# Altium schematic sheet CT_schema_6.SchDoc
size 368 x 245 mm
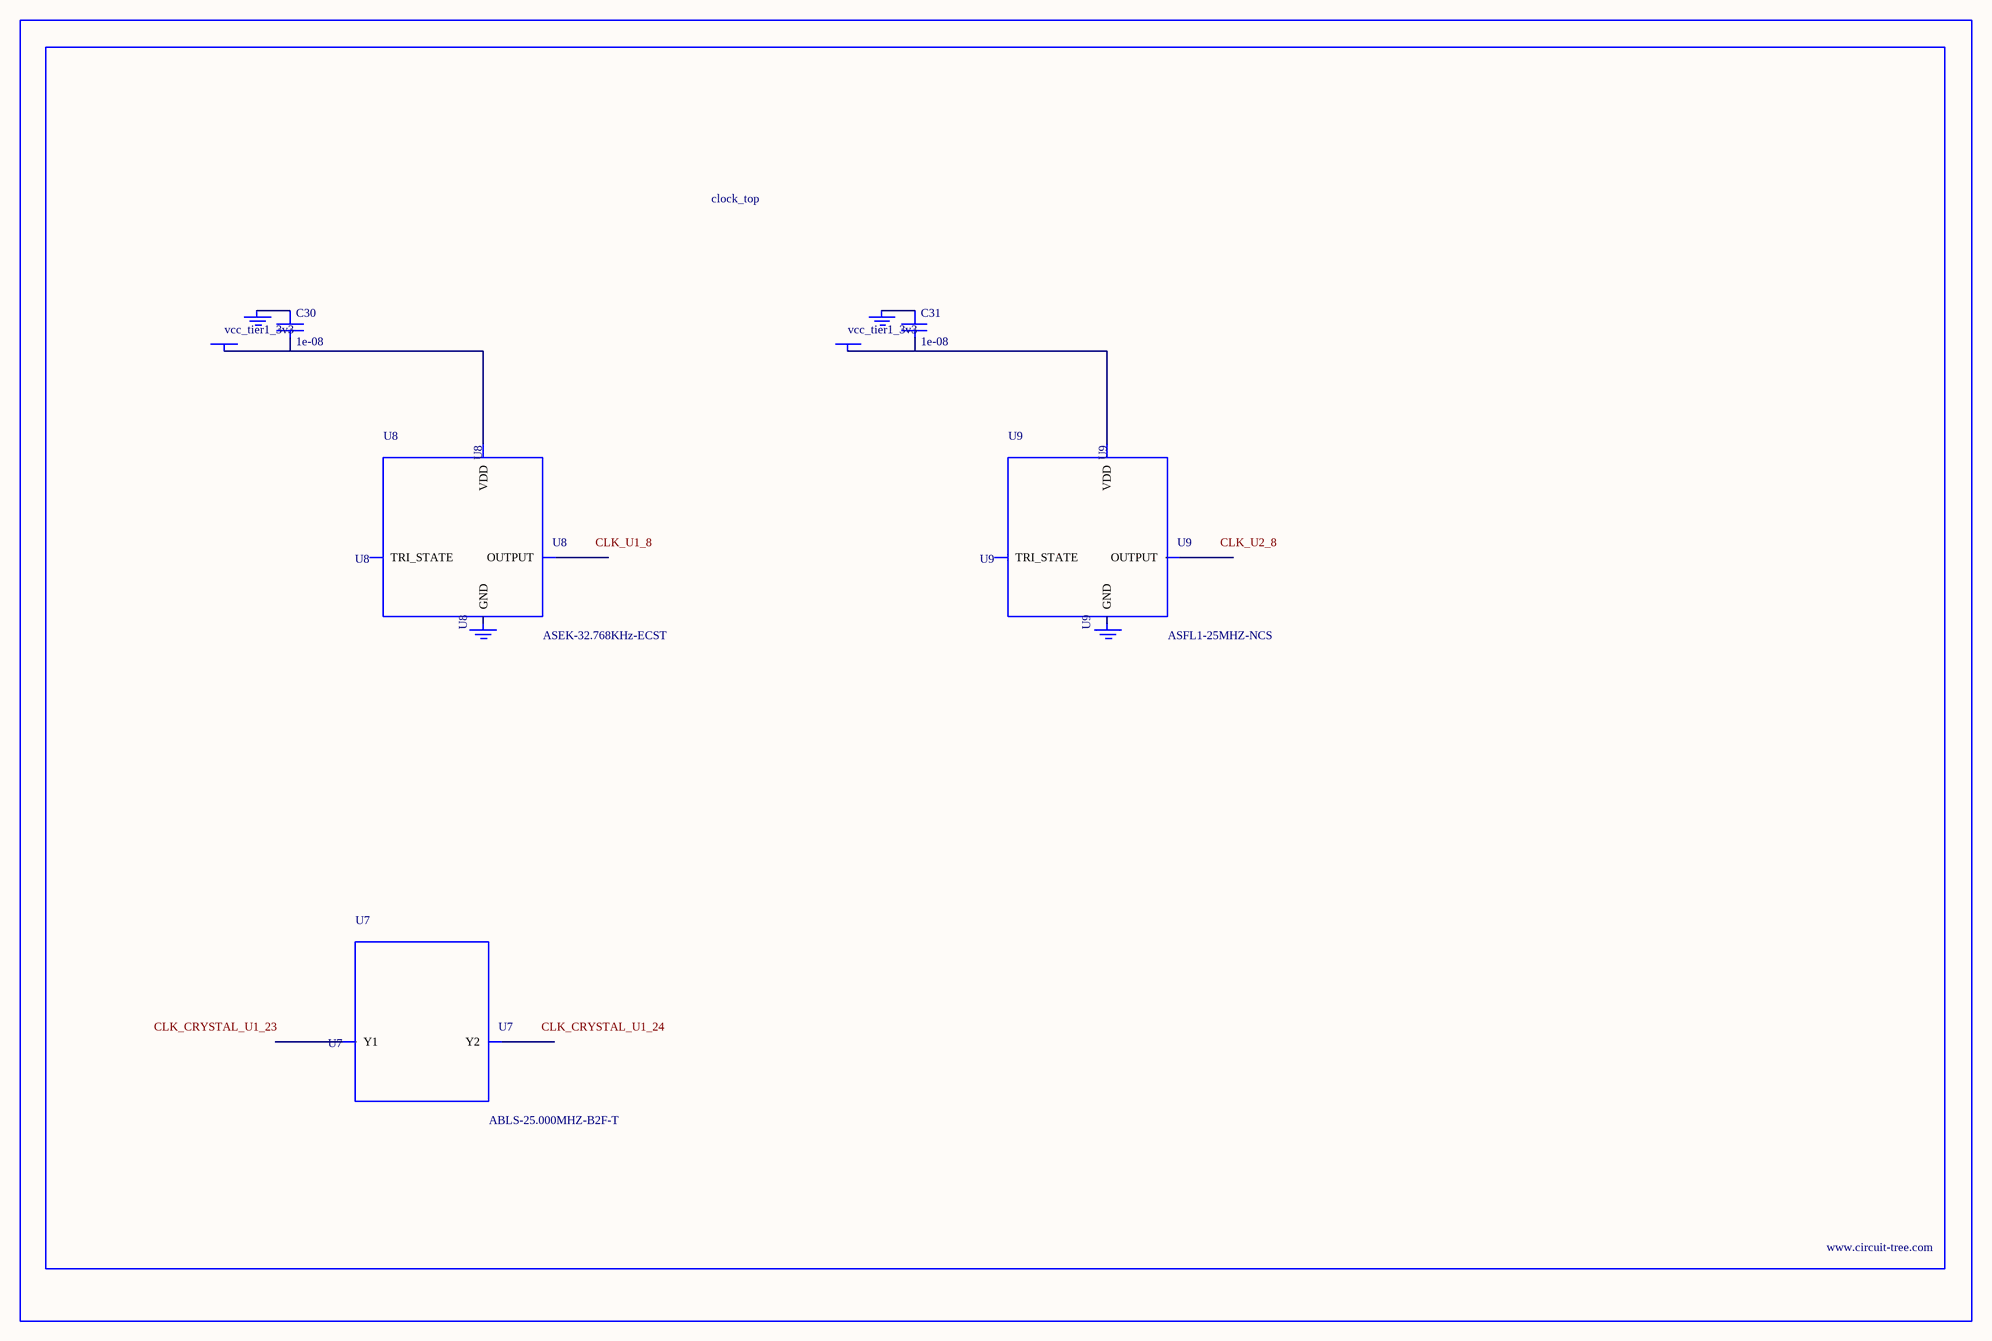
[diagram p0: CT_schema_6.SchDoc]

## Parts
BORDER5  (no value)
C30  1e-08  [C0402]
C31  1e-08  [C0402]
GND_INSTANCE_5_0  (no value)
GND_INSTANCE_5_1  (no value)
GND_INSTANCE_5_2  (no value)
GND_INSTANCE_5_3  (no value)
POWER_INSTANCE_5_0  vcc_tier1_3v3
POWER_INSTANCE_5_1  vcc_tier1_3v3
U7  ABLS-25.000MHZ-B2F-T  [ABLS-25.000MHZ-B2F-T]
U8  ASEK-32.768KHz-ECST  [ASEK]
U9  ASFL1-25MHZ-NCS  [ASFL1]

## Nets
NetC30_1: C30.1 GND_INSTANCE_5_0.0(GND)
NetC30_2: C30.2 POWER_INSTANCE_5_0.0(PWR) U8.4(VDD)
NetC31_1: C31.1 GND_INSTANCE_5_2.0(GND)
NetC31_2: C31.2 POWER_INSTANCE_5_1.0(PWR) U9.4(VDD)

Not connected (* = marked no-connect by the designer): GND_INSTANCE_5_1 0(GND); GND_INSTANCE_5_3 0(GND); U7 1(Y1) 2(Y2); U8 1(TRI_STATE) 2(GND) 3(OUTPUT); U9 1(TRI_STATE) 2(GND) 3(OUTPUT)

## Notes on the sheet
- Labels drawn without touching a wire or pin: CLK_CRYSTAL_U1_23, CLK_CRYSTAL_U1_24, CLK_U1_8, CLK_U2_8

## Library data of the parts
BORDER5 = BORDER_PAGE5
C30 C31 = C0402C103K3RAC
GND_INSTANCE_5_0-GND_INSTANCE_5_3 = GND
POWER_INSTANCE_5_0 POWER_INSTANCE_5_1 = PWR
